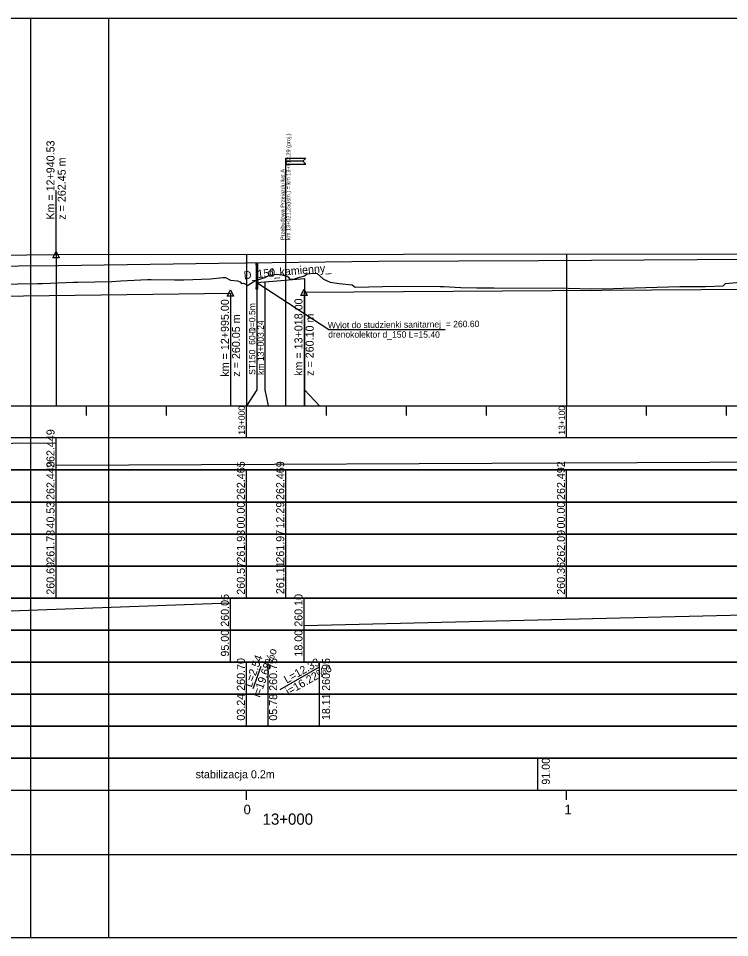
# Model space of a CAD drawing. Extents: x 6445630 to 6518227, y 5499240 to 5511716.
# Drawn here: x 6457560 to 6457782.1, y 5506751.3 to 5507038.3 of the extents above; entities that cross this region are included whole.
import ezdxf

# ---------------------------------------------------------------- set-up
doc = ezdxf.new("R2010")
doc.units = 0
for name, color, linetype in [('TOR_PROF-drenaze', 7, 'Continuous'), ('TOR_PROF-drenokolektory', 7, 'Continuous'), ('TOR_PROF-obiekty+opisy', 7, 'Continuous'), ('TOR_PROF-opisy glowne', 7, 'Continuous'), ('TOR_PROF-opisy pomocnicze', 7, 'Continuous'), ('TOR_PROF-rowy otwarte', 7, 'Continuous'), ('TOR_PROF-studnie i osadniki', 7, 'Continuous'), ('TOR_PROF-tabelka-geometria T1', 7, 'Continuous'), ('TOR_PROF-tabelka-kilometracja', 7, 'Continuous'), ('TOR_PROF-tabelka-odleglosci T1', 7, 'Continuous'), ('TOR_PROF-tabelka-pochylenia proj T1', 7, 'Continuous'), ('TOR_PROF-tabelka-rodzaj rowu T1', 7, 'Continuous'), ('TOR_PROF-tabelka-rodzaj rurociagow T1', 7, 'Continuous'), ('TOR_PROF-tabelka-rowyT1', 7, 'Continuous'), ('TOR_PROF-tabelka-rurociagi T1', 7, 'Continuous'), ('TOR_PROF-tabelka-rzedne istn T1', 7, 'Continuous'), ('TOR_PROF-tabelka-rzedne proj T1', 7, 'Continuous'), ('TOR_PROF-tabelka-teren istniejacy T1', 7, 'Continuous'), ('TOR_PROF-tabelka-warstwa ochronna T1', 7, 'Continuous'), ('TOR_PROF-tor istniejacy T2', 7, 'Continuous'), ('TOR_PROF-tor projektowany', 7, 'Continuous'), ('TOR_PROF-uklad odniesienia', 7, 'Continuous'), ('TOR_PROF-warstwa ochronna', 7, 'Continuous'), ('TOR_RAMKI-dodatkowe3', 7, 'Continuous'), ('TOR_RAMKI-MASKA WYCIECIA', 7, 'Continuous')]:
    doc.layers.add(name, color=color, linetype=linetype)

msp = doc.modelspace()

# ---------------------------------------------------------------- linework, layer by layer
at = {"layer": 'TOR_PROF-drenaze'}
for points in [[(6457634.45, 5506955.8), (6457636.99, 5506956.05)], [(6457636.99, 5506956.05), (6457649.32, 5506957.05)]]:
    msp.add_lwpolyline(points, dxfattribs=at)
at = {"layer": 'TOR_PROF-drenokolektory'}
for points in [[(6457636.99, 5506956.05), (6457636.99, 5506922.3), (6457637.95, 5506917.3), (6457637.95, 5506917.3)], [(6457636.99, 5506956.05), (6457636.99, 5506922.3), (6457637.95, 5506917.3), (6457637.95, 5506917.3)], [(6457649.32, 5506957.05), (6457649.32, 5506922.3), (6457649.32, 5506917.3), (6457649.32, 5506917.3)], [(6457649.32, 5506957.05), (6457649.32, 5506922.3), (6457654.03, 5506917.3), (6457654.03, 5506917.3)], [(6457634.45, 5506955.8), (6457634.45, 5506922.3), (6457631.21, 5506917.3), (6457631.21, 5506917.3)], [(6457634.45, 5506955.8), (6457634.45, 5506922.3), (6457634.45, 5506922.3), (6457634.45, 5506922.3)]]:
    msp.add_lwpolyline(points, dxfattribs=at)
at = {"layer": 'TOR_PROF-obiekty+opisy'}
msp.add_line((6457643.5, 5506917.3), (6457643.5, 5506994.64), dxfattribs=at)
for points in [[(6457649.75, 5506994.64), (6457648.82, 5506993.71), (6457643.5, 5506993.71), (6457643.5, 5506994.64), (6457649.75, 5506994.64)], [(6457649.75, 5506992.77), (6457648.82, 5506993.71), (6457643.5, 5506993.71), (6457643.5, 5506992.77), (6457649.75, 5506992.77)]]:
    msp.add_lwpolyline(points, dxfattribs=at)
at = {"layer": 'TOR_PROF-opisy pomocnicze'}
for p, q in [((6457571.74, 5506964.55), (6457571.74, 5506984.55)), ((6457571.74, 5506964.55), (6457571.74, 5506984.55)), ((6457626.21, 5506952.55), (6457626.21, 5506925.55)), ((6457649.21, 5506952.8), (6457649.21, 5506925.8))]:
    msp.add_line(p, q, dxfattribs=at)
for points in [[(6457571.74, 5506965.55), (6457572.74, 5506963.55), (6457570.74, 5506963.55)], [(6457571.74, 5506965.55), (6457572.74, 5506963.55), (6457570.74, 5506963.55)], [(6457626.21, 5506953.55), (6457627.21, 5506951.55), (6457625.21, 5506951.55)], [(6457649.21, 5506953.8), (6457650.21, 5506951.8), (6457648.21, 5506951.8)]]:
    msp.add_lwpolyline(points, close=True, dxfattribs=at)
at = {"layer": 'TOR_PROF-rowy otwarte'}
for p, q in [((6457649.21, 5506952.8), (6457941.21, 5506954.8)), ((6457431.21, 5506950.05), (6457626.21, 5506952.55))]:
    msp.add_line(p, q, dxfattribs=at)
for points in [[(6457626.21, 5506952.55), (6457626.21, 5506922.3), (6457626.21, 5506917.3), (6457626.21, 5506917.3)], [(6457649.21, 5506952.8), (6457649.21, 5506922.3), (6457649.21, 5506917.3), (6457649.21, 5506917.3)]]:
    msp.add_lwpolyline(points, dxfattribs=at)
at = {"layer": 'TOR_PROF-studnie i osadniki'}
for p, q in [((6457634.2, 5506961.8), (6457634.2, 5506953.8)), ((6457634.2, 5506961.8), (6457634.7, 5506961.8)), ((6457634.7, 5506961.8), (6457634.7, 5506953.8)), ((6457634.2, 5506953.8), (6457634.7, 5506953.8))]:
    msp.add_line(p, q, dxfattribs=at)
for points in [[(6457634.2, 5506961.8), (6457634.7, 5506961.8), (6457634.7, 5506961.3), (6457634.2, 5506961.3)], [(6457634.2, 5506954.3), (6457634.7, 5506954.3), (6457634.7, 5506953.8), (6457634.2, 5506953.8)]]:
    msp.add_lwpolyline(points, close=True, dxfattribs=at)
at = {"layer": 'TOR_PROF-tabelka-geometria T1'}
for points in [[(6452735.25, 5506777.3), (6458247.17, 5506777.3), (6458247.17, 5506779.97), (6458376.27, 5506779.97), (6458376.27, 5506777.3), (6458396.27, 5506777.3), (6458396.27, 5506774.64), (6458525.37, 5506774.64), (6458525.37, 5506777.3), (6458723.83, 5506777.3), (6458723.83, 5506777.3), (6458758.83, 5506774.64), (6458758.83, 5506774.64), (6458827.61, 5506774.64), (6458827.61, 5506774.64), (6458862.61, 5506777.3), (6458862.61, 5506777.3), (6458862.61, 5506777.3), (6458862.61, 5506777.3), (6458897.61, 5506779.97), (6458897.61, 5506779.97), (6458966.4, 5506779.97), (6458966.4, 5506779.97), (6459001.4, 5506777.3)], [(6452331.21, 5506777.3), (6459531.21, 5506777.3)]]:
    msp.add_lwpolyline(points, dxfattribs=at)
at = {"layer": 'TOR_PROF-tabelka-kilometracja'}
for points in [[(6457631.21, 5506794.3), (6457631.21, 5506797.3)], [(6457631.21, 5506794.3), (6457631.21, 5506797.3)], [(6457731.21, 5506794.3), (6457731.21, 5506797.3)]]:
    msp.add_lwpolyline(points, dxfattribs=at)
at = {"layer": 'TOR_PROF-tabelka-odleglosci T1'}
msp.add_lwpolyline([(6452331.21, 5506877.3), (6459531.21, 5506877.3), (6459531.21, 5506887.3), (6452331.21, 5506887.3)], close=True, dxfattribs=at)
for points in [[(6457571.74, 5506877.3), (6457571.74, 5506887.3)], [(6457631.21, 5506877.3), (6457631.21, 5506887.3)], [(6457643.5, 5506877.3), (6457643.5, 5506887.3)], [(6457731.21, 5506877.3), (6457731.21, 5506887.3)]]:
    msp.add_lwpolyline(points, dxfattribs=at)
at = {"layer": 'TOR_PROF-tabelka-pochylenia proj T1'}
msp.add_lwpolyline([(6452331.21, 5506897.3), (6459531.21, 5506897.3), (6459531.21, 5506907.3), (6452331.21, 5506907.3)], close=True, dxfattribs=at)
for points in [[(6457571.74, 5506897.3), (6457571.74, 5506907.3)], [(6456656.74, 5506898.8), (6457571.74, 5506905.8)], [(6457571.74, 5506898.8), (6459091.74, 5506905.8)]]:
    msp.add_lwpolyline(points, dxfattribs=at)
at = {"layer": 'TOR_PROF-tabelka-rodzaj rowu T1'}
for points in [[(6452331.21, 5506837.3), (6459531.21, 5506837.3), (6459531.21, 5506847.3), (6452331.21, 5506847.3)], [(6452331.21, 5506817.3), (6459531.21, 5506817.3), (6459531.21, 5506827.3), (6452331.21, 5506827.3)]]:
    msp.add_lwpolyline(points, close=True, dxfattribs=at)
for points in [[(6457626.21, 5506837.3), (6457626.21, 5506847.3)], [(6457649.21, 5506837.3), (6457649.21, 5506847.3)], [(6457631.21, 5506817.3), (6457631.21, 5506827.3)], [(6457637.95, 5506817.3), (6457637.95, 5506827.3)], [(6457654.03, 5506817.3), (6457654.03, 5506827.3)]]:
    msp.add_lwpolyline(points, dxfattribs=at)
at = {"layer": 'TOR_PROF-tabelka-rowyT1'}
msp.add_lwpolyline([(6452331.21, 5506847.3), (6459531.21, 5506847.3), (6459531.21, 5506857.3), (6452331.21, 5506857.3)], close=True, dxfattribs=at)
for points in [[(6457431.21, 5506848.8), (6457626.21, 5506855.8)], [(6457626.21, 5506847.3), (6457626.21, 5506857.3)], [(6457649.21, 5506847.3), (6457649.21, 5506857.3)], [(6457649.21, 5506848.8), (6457941.21, 5506855.8)]]:
    msp.add_lwpolyline(points, dxfattribs=at)
at = {"layer": 'TOR_PROF-tabelka-rurociagi T1'}
msp.add_lwpolyline([(6452331.21, 5506827.3), (6459531.21, 5506827.3), (6459531.21, 5506837.3), (6452331.21, 5506837.3)], close=True, dxfattribs=at)
for points in [[(6457631.21, 5506827.3), (6457631.21, 5506837.3)], [(6457633.26, 5506829.1), (6457635.8, 5506836.1)], [(6457637.95, 5506827.3), (6457637.95, 5506837.3)], [(6457641.7, 5506828.8), (6457654.03, 5506835.8)], [(6457654.03, 5506827.3), (6457654.03, 5506837.3)]]:
    msp.add_lwpolyline(points, dxfattribs=at)
at = {"layer": 'TOR_PROF-tabelka-rzedne istn T1'}
msp.add_lwpolyline([(6452331.21, 5506867.3), (6459531.21, 5506867.3), (6459531.21, 5506877.3), (6452331.21, 5506877.3)], close=True, dxfattribs=at)
for points in [[(6457571.74, 5506867.3), (6457571.74, 5506877.3)], [(6457631.21, 5506867.3), (6457631.21, 5506877.3)], [(6457643.5, 5506867.3), (6457643.5, 5506877.3)], [(6457731.21, 5506867.3), (6457731.21, 5506877.3)], [(6457571.74, 5506857.3), (6457571.74, 5506867.3)], [(6457571.74, 5506857.3), (6457571.74, 5506867.3)], [(6457571.74, 5506857.3), (6457571.74, 5506867.3)], [(6457631.21, 5506857.3), (6457631.21, 5506867.3)], [(6457631.21, 5506857.3), (6457631.21, 5506867.3)], [(6457631.21, 5506857.3), (6457631.21, 5506867.3)], [(6457643.5, 5506857.3), (6457643.5, 5506867.3)], [(6457643.5, 5506857.3), (6457643.5, 5506867.3)], [(6457643.5, 5506857.3), (6457643.5, 5506867.3)], [(6457731.21, 5506857.3), (6457731.21, 5506867.3)], [(6457731.21, 5506857.3), (6457731.21, 5506867.3)], [(6457731.21, 5506857.3), (6457731.21, 5506867.3)]]:
    msp.add_lwpolyline(points, dxfattribs=at)
at = {"layer": 'TOR_PROF-tabelka-rzedne proj T1'}
for p, q in [((6457634.45, 5506955.8), (6457656.92, 5506941.12)), ((6457656.92, 5506941.12), (6457693.29, 5506941.12))]:
    msp.add_line(p, q, dxfattribs=at)
msp.add_lwpolyline([(6452331.21, 5506887.3), (6459531.21, 5506887.3), (6459531.21, 5506897.3), (6452331.21, 5506897.3)], close=True, dxfattribs=at)
for points in [[(6457571.74, 5506887.3), (6457571.74, 5506897.3)], [(6457631.21, 5506887.3), (6457631.21, 5506897.3)], [(6457643.5, 5506887.3), (6457643.5, 5506897.3)], [(6457731.21, 5506887.3), (6457731.21, 5506897.3)]]:
    msp.add_lwpolyline(points, dxfattribs=at)
at = {"layer": 'TOR_PROF-tabelka-teren istniejacy T1'}
msp.add_lwpolyline([(6452331.21, 5506857.3), (6459531.21, 5506857.3), (6459531.21, 5506867.3), (6452331.21, 5506867.3)], close=True, dxfattribs=at)
msp.add_lwpolyline([(6452331.21, 5506857.3), (6459531.21, 5506857.3), (6459531.21, 5506867.3), (6452331.21, 5506867.3)], close=True, dxfattribs=at)
msp.add_lwpolyline([(6452331.21, 5506857.3), (6459531.21, 5506857.3), (6459531.21, 5506867.3), (6452331.21, 5506867.3)], close=True, dxfattribs=at)
at = {"layer": 'TOR_PROF-tabelka-warstwa ochronna T1'}
msp.add_lwpolyline([(6452331.21, 5506807.3), (6459531.21, 5506807.3), (6459531.21, 5506817.3), (6452331.21, 5506817.3)], close=True, dxfattribs=at)
at = {"layer": 'TOR_PROF-tor istniejacy T2'}
msp.add_lwpolyline([(6457323.35, 5506959.65), (6457375.16, 5506960.05), (6457423.21, 5506960.15), (6457471.72, 5506960.25), (6457522.28, 5506960.7), (6457572.54, 5506961.2), (6457622.63, 5506961.85), (6457672.41, 5506962.5), (6457722.46, 5506962.7), (6457771.97, 5506963.05), (6457821.96, 5506963.35), (6457872.05, 5506963.5), (6457922.09, 5506964.15), (6457971.39, 5506964.65), (6458022.49, 5506965.3), (6458072.79, 5506965.2), (6458106.04, 5506965.15), (6458121.32, 5506965.4), (6458171.76, 5506965.1), (6458221.3, 5506964.95), (6458270.72, 5506964.8), (6458321.69, 5506965.05)], dxfattribs=at)
at = {"layer": 'TOR_PROF-tor projektowany'}
for p, q in [((6457571.74, 5506964.55), (6459091.74, 5506966.6)), ((6457571.74, 5506964.55), (6459091.74, 5506966.6)), ((6456656.74, 5506956.4), (6457571.74, 5506964.55)), ((6456656.74, 5506956.4), (6457571.74, 5506964.55))]:
    msp.add_line(p, q, dxfattribs=at)
for points in [[(6457631.21, 5506964.63), (6457631.21, 5506922.3), (6457631.21, 5506917.3), (6457631.21, 5506917.3)], [(6457631.21, 5506964.63), (6457631.21, 5506922.3), (6457631.21, 5506917.3), (6457631.21, 5506917.3)], [(6457731.21, 5506964.76), (6457731.21, 5506922.3), (6457731.21, 5506917.3), (6457731.21, 5506917.3)], [(6457731.21, 5506964.76), (6457731.21, 5506922.3), (6457731.21, 5506917.3), (6457731.21, 5506917.3)], [(6457571.74, 5506964.55), (6457571.74, 5506922.3), (6457571.74, 5506917.3), (6457571.74, 5506917.3)], [(6457571.74, 5506964.55), (6457571.74, 5506922.3), (6457571.74, 5506917.3), (6457571.74, 5506917.3)], [(6457571.74, 5506964.55), (6457571.74, 5506922.3), (6457571.74, 5506917.3), (6457571.74, 5506917.3)], [(6457571.74, 5506964.55), (6457571.74, 5506922.3), (6457571.74, 5506917.3), (6457571.74, 5506917.3)]]:
    msp.add_lwpolyline(points, dxfattribs=at)
at = {"layer": 'TOR_PROF-uklad odniesienia'}
for p, q in [((6452331.21, 5506917.3), (6459531.21, 5506917.3)), ((6457581.21, 5506914.3), (6457581.21, 5506917.3)), ((6457606.21, 5506914.3), (6457606.21, 5506917.3)), ((6457631.21, 5506907.3), (6457631.21, 5506917.3)), ((6457656.21, 5506914.3), (6457656.21, 5506917.3)), ((6457681.21, 5506914.3), (6457681.21, 5506917.3)), ((6457706.21, 5506914.3), (6457706.21, 5506917.3)), ((6457731.21, 5506907.3), (6457731.21, 5506917.3)), ((6457756.21, 5506914.3), (6457756.21, 5506917.3)), ((6457781.21, 5506914.3), (6457781.21, 5506917.3))]:
    msp.add_line(p, q, dxfattribs=at)
at = {"layer": 'TOR_PROF-warstwa ochronna'}
msp.add_lwpolyline([(6452331.21, 5506797.3), (6459531.21, 5506797.3), (6459531.21, 5506807.3), (6452331.21, 5506807.3)], close=True, dxfattribs=at)
msp.add_lwpolyline([(6457722.21, 5506797.3), (6457722.21, 5506807.3)], dxfattribs=at)
at = {"layer": 'TOR_RAMKI-dodatkowe3'}
for p, q in [((6457578.58, 5506955.95), (6457589.19, 5506956.16)), ((6457589.19, 5506956.16), (6457591.94, 5506956.32)), ((6457591.94, 5506956.32), (6457600.31, 5506956.75)), ((6457600.31, 5506956.75), (6457601.44, 5506956.8)), ((6457601.44, 5506956.8), (6457608.68, 5506956.69)), ((6457608.68, 5506956.69), (6457610.79, 5506956.71)), ((6457610.79, 5506956.71), (6457611.69, 5506956.72)), ((6457611.69, 5506956.72), (6457619.98, 5506957.02)), ((6457619.98, 5506957.02), (6457623.86, 5506957.35)), ((6457623.86, 5506957.35), (6457624.62, 5506957.41)), ((6457624.62, 5506957.41), (6457626.23, 5506956.52)), ((6457626.23, 5506956.52), (6457628.45, 5506956.33)), ((6457628.45, 5506956.33), (6457629.25, 5506956.05)), ((6457629.25, 5506956.05), (6457629.64, 5506955.56)), ((6457631.86, 5506955.12), (6457633.87, 5506956.37)), ((6457633.87, 5506956.37), (6457636.91, 5506957.44)), ((6457636.91, 5506957.44), (6457637.52, 5506957.75)), ((6457637.52, 5506957.75), (6457638.52, 5506958.18)), ((6457638.52, 5506958.18), (6457640.5, 5506958.47)), ((6457640.5, 5506958.47), (6457642.38, 5506958.28)), ((6457642.38, 5506958.28), (6457644.22, 5506957.58)), ((6457644.22, 5506957.58), (6457644.61, 5506956.95)), ((6457644.61, 5506956.95), (6457645.69, 5506956.9)), ((6457645.69, 5506956.9), (6457646.3, 5506957.03)), ((6457646.3, 5506957.03), (6457646.53, 5506957.07)), ((6457646.53, 5506957.07), (6457647.78, 5506957.51)), ((6457647.78, 5506957.51), (6457649.18, 5506957.85)), ((6457649.18, 5506957.85), (6457650.18, 5506958.57)), ((6457650.18, 5506958.57), (6457652.16, 5506958.8)), ((6457652.16, 5506958.8), (6457653.33, 5506958.6)), ((6457653.33, 5506958.6), (6457655.31, 5506956.89)), ((6457655.31, 5506956.89), (6457657.32, 5506955.94)), ((6457780.88, 5506955.5), (6457795.11, 5506956.88)), ((6457543.89, 5506955.18), (6457565.97, 5506955.48)), ((6457565.97, 5506955.48), (6457566.29, 5506955.51)), ((6457566.29, 5506955.51), (6457567.45, 5506955.56)), ((6457567.45, 5506955.56), (6457577.14, 5506955.94)), ((6457577.14, 5506955.94), (6457577.89, 5506955.93)), ((6457577.89, 5506955.93), (6457578.58, 5506955.95)), ((6457629.64, 5506955.56), (6457630.3, 5506955.66)), ((6457630.3, 5506955.66), (6457630.97, 5506955.29)), ((6457630.97, 5506955.29), (6457631.64, 5506954.91)), ((6457631.64, 5506954.91), (6457631.74, 5506955.02)), ((6457631.74, 5506955.02), (6457631.86, 5506955.12)), ((6457657.32, 5506955.94), (6457660.12, 5506955.57)), ((6457660.12, 5506955.57), (6457664.26, 5506955.06)), ((6457664.26, 5506955.06), (6457665.2, 5506954.37)), ((6457665.2, 5506954.37), (6457677.98, 5506954.68)), ((6457677.98, 5506954.68), (6457691.72, 5506954.57)), ((6457691.72, 5506954.57), (6457692.86, 5506954.56)), ((6457692.86, 5506954.56), (6457698.19, 5506954.31)), ((6457698.19, 5506954.31), (6457703.21, 5506954.17)), ((6457703.21, 5506954.17), (6457708.46, 5506954.18)), ((6457708.46, 5506954.18), (6457731.66, 5506954.11)), ((6457731.66, 5506954.11), (6457739.15, 5506953.9)), ((6457739.15, 5506953.9), (6457745.86, 5506953.95)), ((6457745.86, 5506953.95), (6457748.94, 5506954.05)), ((6457748.94, 5506954.05), (6457766.63, 5506954.64)), ((6457766.63, 5506954.64), (6457772, 5506954.58)), ((6457772, 5506954.58), (6457774.63, 5506954.61)), ((6457774.63, 5506954.61), (6457780.16, 5506954.75)), ((6457780.16, 5506954.75), (6457780.88, 5506955.5))]:
    msp.add_line(p, q, dxfattribs=at)
at = {"layer": 'TOR_RAMKI-MASKA WYCIECIA'}
for points in [[(6455538.23, 5506751.3), (6457588.23, 5506751.3), (6457588.23, 5507038.3), (6455538.23, 5507038.3)], [(6457563.7, 5506751.3), (6459553.7, 5506751.3), (6459553.7, 5507038.3), (6457563.7, 5507038.3)]]:
    msp.add_lwpolyline(points, close=True, dxfattribs=at)

# ---------------------------------------------------------------- texts
at = {"layer": 'TOR_PROF-drenaze'}
for s, rotation, p in [('D_150  ', 5.6212, (6457630.49, 5506956.81)), ('d_kamienny_  ', 4.637, (6457637.93, 5506957.61))]:
    msp.add_text(s, height=2.5, rotation=rotation, dxfattribs=at).set_placement(p)
at = {"layer": 'TOR_PROF-obiekty+opisy'}
for s, p in [('km 13+021,25(istn.) = km 13+012,29 (proj.)', (6457644.92, 5506969.13)), ('Przebudowa Przejazdu kat.A', (6457643.13, 5506969.11))]:
    msp.add_text(s, height=1.25, rotation=90, dxfattribs=at).set_placement(p)
at = {"layer": 'TOR_PROF-opisy glowne'}
for s, rotation, p in [('D=0.5m', 90, (6457633.98, 5506939.95)), ('km 13+003.24', 90, (6457636.64, 5506927)), ('Wylot do studzienki sanitarnej  = 260.60', 0.4945, (6457656.63, 5506941.52)), ('ST150_60-1', 90, (6457633.98, 5506927)), ('drenokolektor d_150 L=15.40', 359.8879, (6457656.76, 5506938.64))]:
    msp.add_text(s, height=2, rotation=rotation, dxfattribs=at).set_placement(p)
at = {"layer": 'TOR_PROF-opisy pomocnicze'}
for s, p in [('Km = 12+940.53', (6457571.24, 5506975.45)), ('Km = 12+940.53', (6457571.24, 5506975.45)), ('z = 262.45 m', (6457574.74, 5506975.45)), ('z = 262.45 m', (6457574.74, 5506975.45)), ('km = 12+995.00', (6457625.71, 5506926.45)), ('km = 13+018.00', (6457648.71, 5506926.7)), ('z = 260.05 m', (6457629.21, 5506926.45)), ('z = 260.10 m', (6457652.21, 5506926.7))]:
    msp.add_text(s, height=2.5, rotation=90, dxfattribs=at).set_placement(p)
at = {"layer": 'TOR_PROF-tabelka-kilometracja'}
for s, p in [('0', (6457630.32, 5506789.8)), ('1', (6457730.56, 5506789.8))]:
    msp.add_text(s, height=3, dxfattribs=at).set_placement(p)
msp.add_text('13+000', height=3.5, rotation=360, dxfattribs=at).set_placement((6457636.26, 5506786.55))
at = {"layer": 'TOR_PROF-tabelka-odleglosci T1'}
for s, p in [('40.53', (6457571.24, 5506879.04)), ('00.00', (6457630.71, 5506879.04)), ('12.29', (6457643, 5506879.04)), ('00.00', (6457730.71, 5506879.04))]:
    msp.add_text(s, height=2.5, rotation=90, dxfattribs=at).set_placement(p)
at = {"layer": 'TOR_PROF-tabelka-pochylenia proj T1'}
msp.add_text('262.449', height=2.5, rotation=90, dxfattribs=at).set_placement((6457571.24, 5506897.94))
at = {"layer": 'TOR_PROF-tabelka-rodzaj rowu T1'}
for s, p in [('95.00', (6457625.71, 5506839.05)), ('18.00', (6457648.71, 5506839.05))]:
    msp.add_text(s, height=2.5, rotation=90, dxfattribs=at).set_placement(p)
at = {"layer": 'TOR_PROF-tabelka-rodzaj rurociagow T1'}
for s, p in [('03.24', (6457630.71, 5506819.05)), ('05.78', (6457640.8, 5506819.04)), ('18.11', (6457657.32, 5506819.21))]:
    msp.add_text(s, height=2.5, rotation=90, dxfattribs=at).set_placement(p)
at = {"layer": 'TOR_PROF-tabelka-rowyT1'}
for s, p in [('260.05', (6457625.71, 5506848.36)), ('260.10', (6457648.71, 5506848.37))]:
    msp.add_text(s, height=2.5, rotation=90, dxfattribs=at).set_placement(p)
at = {"layer": 'TOR_PROF-tabelka-rurociagi T1'}
for s, rotation, p in [('i=19.68%o', 70.0561, (6457635.38, 5506826.14)), ('260.70', 90, (6457630.71, 5506828.37)), ('L=2.54', 70.0561, (6457632.79, 5506829.27)), ('260.75', 90, (6457640.8, 5506828.36)), ('L=12.33', 29.5863, (6457643.79, 5506830.56)), ('260.95', 90, (6457657.32, 5506828.36)), ('i=16.22%o', 29.5863, (6457644.33, 5506826.84))]:
    msp.add_text(s, height=2.5, rotation=rotation, dxfattribs=at).set_placement(p)
at = {"layer": 'TOR_PROF-tabelka-rzedne istn T1'}
for s, p in [('261.78', (6457571.24, 5506868.36)), ('261.93', (6457630.71, 5506868.37)), ('261.97', (6457643, 5506868.37)), ('262.09', (6457730.71, 5506868.37)), ('260.69', (6457571.24, 5506858.37)), ('260.57', (6457630.71, 5506858.37)), ('261.11', (6457643, 5506858.54)), ('260.36', (6457730.71, 5506858.36))]:
    msp.add_text(s, height=2.5, rotation=90, dxfattribs=at).set_placement(p)
at = {"layer": 'TOR_PROF-tabelka-rzedne proj T1'}
for s, p in [('262.449', (6457571.24, 5506887.94)), ('262.465', (6457630.71, 5506887.93)), ('262.469', (6457643, 5506887.94)), ('262.492', (6457730.71, 5506887.95))]:
    msp.add_text(s, height=2.5, rotation=90, dxfattribs=at).set_placement(p)
at = {"layer": 'TOR_PROF-uklad odniesienia'}
for s, p in [('13+000', (6457630.71, 5506908.32)), ('13+100', (6457730.71, 5506908.32))]:
    msp.add_text(s, height=2, rotation=90, dxfattribs=at).set_placement(p)
at = {"layer": 'TOR_PROF-warstwa ochronna'}
msp.add_text('91.00', height=2.5, rotation=90, dxfattribs=at).set_placement((6457725.97, 5506799.05))
msp.add_text('stabilizacja 0.2m', height=2.5, dxfattribs=at).set_placement((6457615.33, 5506801.05))

doc.saveas('drawing.dxf')
